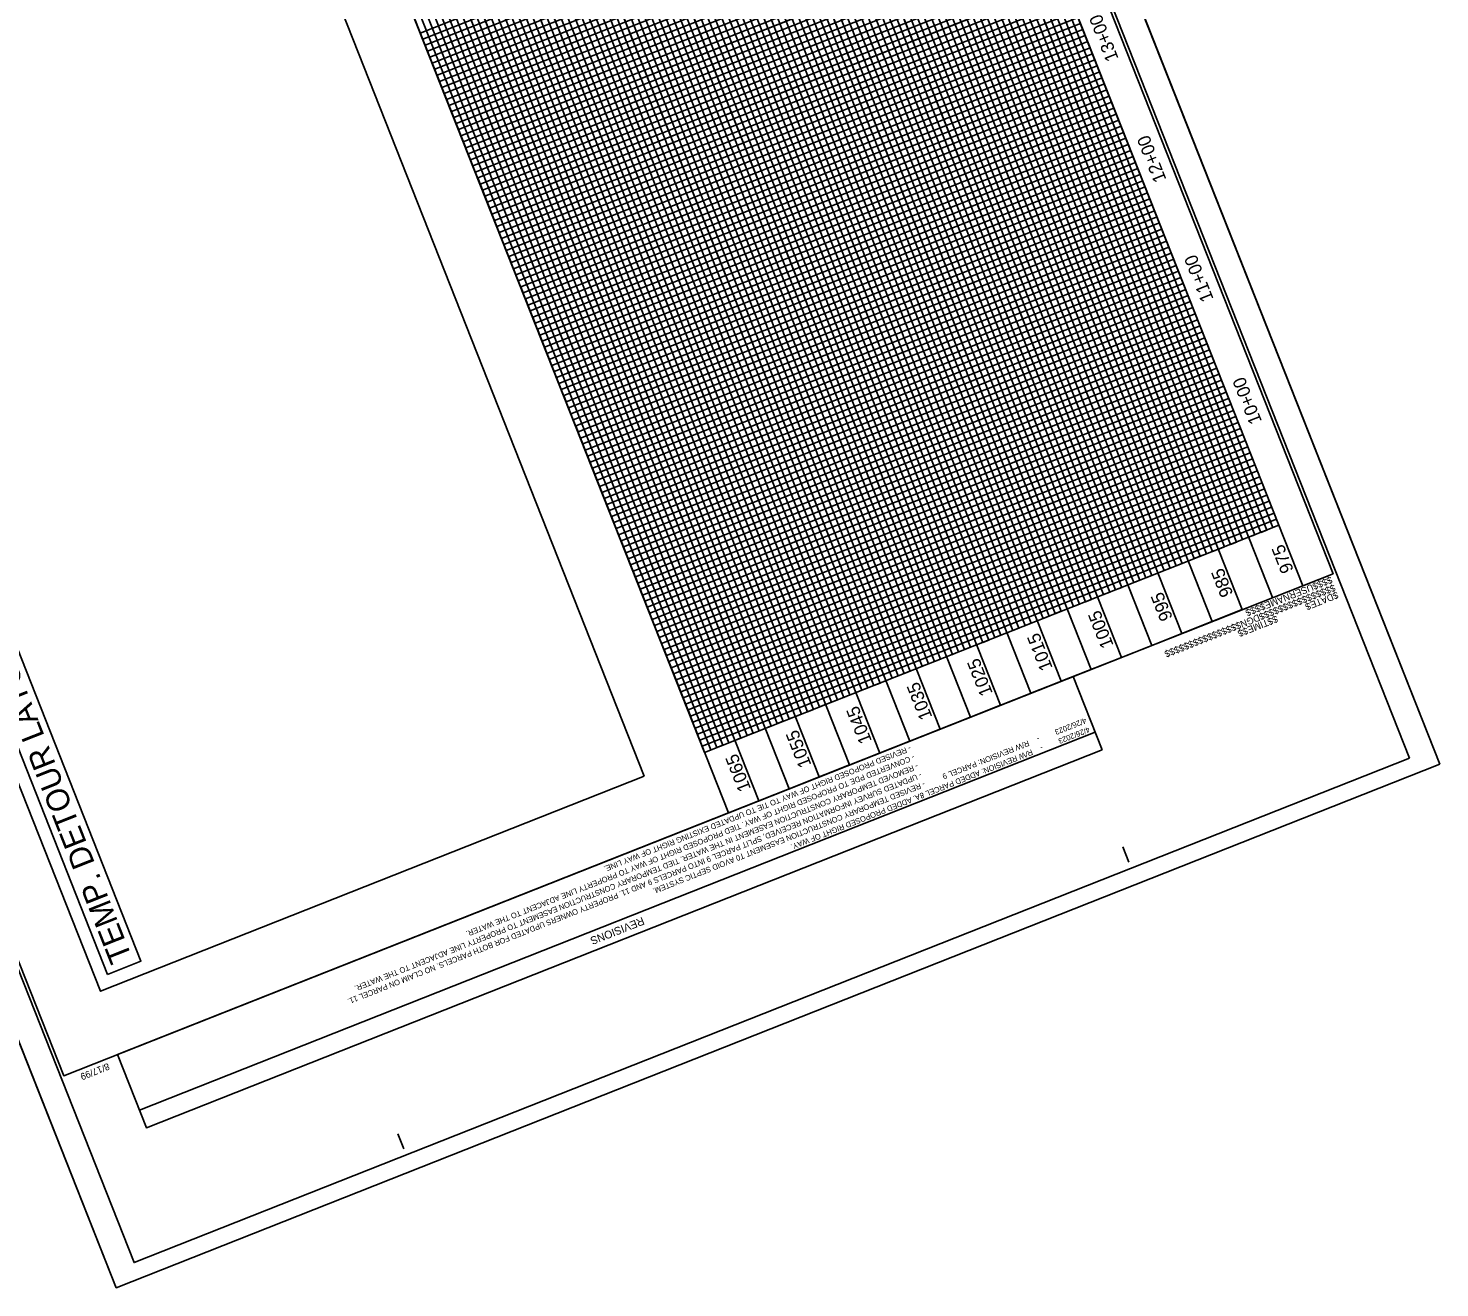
# Model space of a CAD drawing. Extents: x 1250120 to 1251758, y 748130 to 750098.
# Drawn here: x 1250672 to 1251758, y 748130 to 749099 of the extents above; entities that cross this region are included whole.
import ezdxf

# ---------------------------------------------------------------- set-up
doc = ezdxf.new("R2010")
doc.units = 0
for name, color, linetype in [('Exist Vertical Profile Horizontal Axis Label Major', 7, 'Continuous'), ('Exist Vertical Profile Vertical Axis Label', 7, 'Continuous'), ('Prop DSN Text', 7, 'Continuous'), ('Sheet Block Revision CELL', 7, 'Continuous'), ('Sheet Block System Information CELL', 7, 'Continuous'), ('Sheet Cutting Line CELL', 7, 'Continuous'), ('Sheet Detail CELL', 7, 'Continuous'), ('Sheet DOT Grid CELL', 7, 'Continuous'), ('Sheet Layout Plan Border', 7, 'Continuous'), ('Sheet Layout Profile Border Port 2', 7, 'Continuous'), ('Sheet Plan And Profile CELL', 7, 'Continuous'), ('Sheet Plot Border Inside CELL', 7, 'Continuous'), ('Sheet Plot Border Outside CELL', 7, 'Continuous'), ('Sheet Profile Grid Major CELL', 7, 'Continuous'), ('Sheet Profile Grid Middle CELL', 7, 'Continuous'), ('Sheet Profile Grid Minor CELL', 7, 'Continuous')]:
    doc.layers.add(name, color=color, linetype=linetype)

msp = doc.modelspace()

# ---------------------------------------------------------------- linework, layer by layer
at = {"layer": 'Sheet Block Revision CELL'}
msp.add_line((1251492.5, 748557.2), (1250757.2, 748266.4), dxfattribs=at)
msp.add_lwpolyline([(1251497.8, 748543.6), (1250762.6, 748252.9), (1250740.3, 748309.2), (1251475.6, 748599.9)], close=True, dxfattribs=at)
at = {"layer": 'Sheet Block System Information CELL'}
msp.add_line((1251675.5, 748679), (1251675.5, 748679), dxfattribs=at)
at = {"layer": 'Sheet Cutting Line CELL'}
for p, q in [((1251757.6, 748532.4), (1251138.6, 750098)), ((1250120.3, 749695.3), (1250739.4, 748129.8)), ((1250739.4, 748129.8), (1251757.6, 748532.4))]:
    msp.add_line(p, q, dxfattribs=at)
at = {"layer": 'Sheet Detail CELL'}
msp.add_lwpolyline([(1250732.8, 748370.8), (1250758.4, 748380.9), (1250644.4, 748669), (1250618.8, 748658.9)], close=True, dxfattribs=at)
at = {"layer": 'Sheet DOT Grid CELL'}
for p, q in [((1251629, 748660.6), (1251077.4, 750055.5)), ((1251582.5, 748642.2), (1251030.9, 750037.1)), ((1251536, 748623.8), (1250984.4, 750018.7)), ((1251489.5, 748605.4), (1250937.9, 750000.4)), ((1251443, 748587.1), (1250891.4, 749982)), ((1251396.5, 748568.7), (1250844.9, 749963.6)), ((1251350, 748550.3), (1250798.5, 749945.2)), ((1251303.5, 748531.9), (1250752, 749926.8)), ((1251257, 748513.5), (1250705.5, 749908.4)), ((1251210.5, 748495.1), (1250659, 749890)), ((1250989.9, 749053.1), (1251431.6, 749227.8)), ((1251008.3, 749006.6), (1251450, 749181.3)), ((1251026.7, 748960.1), (1251468.4, 749134.8)), ((1251045.1, 748913.6), (1251486.8, 749088.3)), ((1251063.4, 748867.1), (1251505.2, 749041.8)), ((1251081.8, 748820.6), (1251523.5, 748995.3)), ((1251100.2, 748774.1), (1251541.9, 748948.8)), ((1251118.6, 748727.6), (1251560.3, 748902.3)), ((1251137, 748681.1), (1251578.7, 748855.8)), ((1251155.4, 748634.6), (1251597.1, 748809.3)), ((1251173.8, 748588.1), (1251615.5, 748762.8)), ((1251192.1, 748541.6), (1251633.9, 748716.3))]:
    msp.add_line(p, q, dxfattribs=at)
at = {"layer": 'Sheet Layout Plan Border'}
msp.add_lwpolyline([(1251145.6, 748523.2), (1250727.2, 748357.8), (1250285.9, 749473.7), (1250436.1, 749533), (1250362.5, 749719.1), (1250630.8, 749825.2)], close=True, dxfattribs=at)
at = {"layer": 'Sheet Layout Profile Border Port 2'}
msp.add_lwpolyline([(1251192.1, 748541.6), (1250677.3, 749843.5), (1251119.1, 750018.2), (1251633.9, 748716.3)], close=True, dxfattribs=at)
at = {"layer": 'Sheet Plan And Profile CELL'}
for p, q in [((1251100.7, 750064.7), (1251652.2, 748669.8)), ((1251675.5, 748679), (1251675.5, 748679)), ((1251675.5, 748679), (1251675.5, 748679)), ((1251675.5, 748679), (1251675.5, 748679)), ((1251675.5, 748679), (1251675.5, 748679)), ((1251675.5, 748679), (1251675.5, 748679)), ((1251518.5, 748457.2), (1251513.9, 748468.9)), ((1250960.6, 748236.6), (1250956, 748248.2))]:
    msp.add_line(p, q, dxfattribs=at)
msp.add_lwpolyline([(1250147.5, 749687.8), (1250699.1, 748292.9), (1251675.5, 748679), (1251123.9, 750073.9)], close=True, dxfattribs=at)
at = {"layer": 'Sheet Plot Border Inside CELL'}
msp.add_lwpolyline([(1251734.3, 748537.2), (1251121.7, 750086.4), (1250140.6, 749698.5), (1250753.2, 748149.2)], close=True, dxfattribs=at)
at = {"layer": 'Sheet Plot Border Outside CELL'}
msp.add_lwpolyline([(1251757.6, 748532.4), (1251138.6, 750098), (1250120.3, 749695.3), (1250739.4, 748129.8)], close=True, dxfattribs=at)
at = {"layer": 'Sheet Profile Grid Major CELL'}
for points in [[(1251077.4, 750055.5), (1251629, 748660.6)], [(1250984.4, 750018.7), (1251536, 748623.8), (1251582.5, 748642.2), (1251030.9, 750037.1)], [(1250891.4, 749982), (1251443, 748587.1), (1251489.5, 748605.4), (1250937.9, 750000.4)], [(1250798.5, 749945.2), (1251350, 748550.3), (1251396.5, 748568.7), (1250844.9, 749963.6)], [(1250705.5, 749908.4), (1251257, 748513.5), (1251303.5, 748531.9), (1250752, 749926.8)], [(1251210.5, 748495.1), (1250659, 749890)], [(1251450, 749181.3), (1251008.3, 749006.6), (1250989.9, 749053.1), (1251431.6, 749227.8)], [(1251486.8, 749088.3), (1251045.1, 748913.6), (1251026.7, 748960.1), (1251468.4, 749134.8)], [(1251523.5, 748995.3), (1251081.8, 748820.6), (1251063.4, 748867.1), (1251505.2, 749041.8)], [(1251560.3, 748902.3), (1251118.6, 748727.6), (1251100.2, 748774.1), (1251541.9, 748948.8)], [(1251597.1, 748809.3), (1251155.4, 748634.6), (1251137, 748681.1), (1251578.7, 748855.8)], [(1251633.9, 748716.3), (1251192.1, 748541.6), (1251173.8, 748588.1), (1251615.5, 748762.8)], [(1251210.5, 748495.1), (1251652.2, 748669.8)]]:
    msp.add_lwpolyline(points, dxfattribs=at)
at = {"layer": 'Sheet Profile Grid Middle CELL'}
for p, q in [((1251605.7, 748651.4), (1251054.2, 750046.3)), ((1251007.7, 750027.9), (1251559.2, 748633)), ((1251512.8, 748614.6), (1250961.2, 750009.6)), ((1250914.7, 749991.2), (1251466.3, 748596.3)), ((1251419.8, 748577.9), (1250868.2, 749972.8)), ((1250821.7, 749954.4), (1251373.3, 748559.5)), ((1251326.8, 748541.1), (1250775.2, 749936)), ((1250728.7, 749917.6), (1251280.3, 748522.7)), ((1251233.8, 748504.3), (1250682.2, 749899.2)), ((1251559.2, 748633), (1251605.7, 748651.4)), ((1251466.3, 748596.3), (1251512.8, 748614.6)), ((1251373.3, 748559.5), (1251419.8, 748577.9)), ((1251280.3, 748522.7), (1251326.8, 748541.1))]:
    msp.add_line(p, q, dxfattribs=at)
for points in [[(1251440.8, 749204.5), (1250999.1, 749029.9), (1250980.7, 749076.3), (1251422.4, 749251)], [(1251477.6, 749111.5), (1251035.9, 748936.9), (1251017.5, 748983.4), (1251459.2, 749158)], [(1251514.4, 749018.5), (1251072.6, 748843.9), (1251054.2, 748890.4), (1251496, 749065)], [(1251551.1, 748925.5), (1251109.4, 748750.9), (1251091, 748797.4), (1251532.7, 748972)], [(1251587.9, 748832.5), (1251146.2, 748657.9), (1251127.8, 748704.4), (1251569.5, 748879)], [(1251624.7, 748739.5), (1251182.9, 748564.9), (1251164.6, 748611.4), (1251606.3, 748786)]]:
    msp.add_lwpolyline(points, dxfattribs=at)
at = {"layer": 'Sheet Profile Grid Minor CELL'}
for points in [[(1251629.2, 748714.5), (1251114.4, 750016.4), (1251109.8, 750014.5), (1251624.6, 748712.6), (1251619.9, 748710.8), (1251105.1, 750012.7), (1251100.5, 750010.9), (1251615.3, 748708.9), (1251610.6, 748707.1), (1251606, 748705.3), (1251091.2, 750007.2), (1251086.5, 750005.3), (1251601.3, 748703.4), (1251596.7, 748701.6), (1251081.9, 750003.5), (1251077.2, 750001.7), (1251592, 748699.7), (1251587.4, 748697.9), (1251582.7, 748696.1), (1251067.9, 749998), (1251063.3, 749996.1), (1251578.1, 748694.2), (1251573.4, 748692.4), (1251058.6, 749994.3)], [(1251573.4, 748692.4), (1251568.8, 748690.6), (1251054, 749992.5)], [(1251035.4, 749985.1), (1251550.2, 748683.2), (1251545.5, 748681.4), (1251030.7, 749983.3)], [(1251044.7, 749988.8), (1251559.5, 748686.9), (1251554.8, 748685), (1251040, 749987)], [(1250998.2, 749970.4), (1251513, 748668.5), (1251508.3, 748666.7), (1250993.5, 749968.6)], [(1251012.1, 749975.9), (1251526.9, 748674), (1251522.3, 748672.2), (1251007.5, 749974.1)], [(1251021.4, 749979.6), (1251536.2, 748677.7), (1251531.6, 748675.8), (1251016.8, 749977.8)], [(1250974.9, 749961.2), (1251489.7, 748659.3), (1251485.1, 748657.5), (1250970.3, 749959.4)], [(1250988.9, 749966.7), (1251503.7, 748664.8), (1251499, 748663), (1250984.2, 749964.9)], [(1250942.4, 749948.3), (1251457.2, 748646.4), (1251452.5, 748644.6), (1250937.7, 749946.5)], [(1250951.7, 749952), (1251466.5, 748650.1), (1251461.8, 748648.3), (1250947, 749950.2)], [(1250965.6, 749957.5), (1251480.4, 748655.6), (1251475.8, 748653.8), (1250961, 749955.7)], [(1250919.1, 749939.2), (1251433.9, 748637.2), (1251429.3, 748635.4), (1250914.5, 749937.3)], [(1250928.4, 749942.8), (1251443.2, 748640.9), (1251438.6, 748639.1), (1250923.8, 749941)], [(1250895.9, 749930), (1251410.7, 748628), (1251406, 748626.2), (1250891.2, 749928.1)], [(1250905.2, 749933.6), (1251420, 748631.7), (1251415.3, 748629.9), (1250900.5, 749931.8)], [(1250872.6, 749920.8), (1251387.4, 748618.9), (1251382.8, 748617), (1250868, 749918.9)], [(1250881.9, 749924.4), (1251396.7, 748622.5), (1251392.1, 748620.7), (1250877.3, 749922.6)], [(1250835.4, 749906.1), (1251350.2, 748604.1), (1251345.6, 748602.3), (1250830.8, 749904.2)], [(1250849.4, 749911.6), (1251364.2, 748609.7), (1251359.5, 748607.8), (1250844.7, 749909.7)], [(1250858.7, 749915.3), (1251373.5, 748613.3), (1251368.8, 748611.5), (1250854, 749913.4)], [(1250812.2, 749896.9), (1251327, 748594.9), (1251322.3, 748593.1), (1250807.5, 749895)], [(1250826.1, 749902.4), (1251340.9, 748600.5), (1251336.3, 748598.6), (1250821.5, 749900.5)], [(1250779.6, 749884), (1251294.4, 748582.1), (1251289.8, 748580.2), (1250775, 749882.2)], [(1250788.9, 749887.7), (1251303.7, 748585.8), (1251299.1, 748583.9), (1250784.3, 749885.8)], [(1250802.9, 749893.2), (1251317.7, 748591.3), (1251313, 748589.4), (1250798.2, 749891.4)], [(1250751.7, 749873), (1251266.5, 748571), (1251261.9, 748569.2), (1251257.2, 748567.4), (1250742.4, 749869.3)], [(1250761, 749876.6), (1251275.8, 748574.7), (1251271.2, 748572.9), (1250756.4, 749874.8)], [(1251289.8, 748580.2), (1251285.1, 748578.4), (1251280.5, 748576.6), (1250765.7, 749878.5)], [(1250728.5, 749863.8), (1251243.3, 748561.9), (1251238.6, 748560), (1251234, 748558.2), (1250719.2, 749860.1)], [(1250737.8, 749867.5), (1251252.6, 748565.5), (1251247.9, 748563.7), (1250733.1, 749865.6)], [(1250705.2, 749854.6), (1251220, 748552.7), (1251215.4, 748550.8), (1251210.7, 748549), (1250695.9, 749850.9)], [(1250714.5, 749858.3), (1251229.3, 748556.3), (1251224.7, 748554.5), (1250709.9, 749856.4)], [(1250682, 749845.4), (1251196.8, 748543.5)], [(1250691.3, 749849.1), (1251206.1, 748547.1), (1251201.4, 748545.3), (1250686.6, 749847.2)], [(1251416.9, 749265), (1250975.2, 749090.3), (1250973.3, 749094.9), (1251415.1, 749269.6)], [(1251420.6, 749255.7), (1250978.9, 749081), (1250977, 749085.6), (1251418.7, 749260.3)], [(1251426.1, 749241.7), (1250984.4, 749067), (1250982.5, 749071.7), (1251424.3, 749246.4)], [(1251429.8, 749232.4), (1250988.1, 749057.7), (1250986.2, 749062.4), (1251427.9, 749237.1)], [(1251435.3, 749218.5), (1250993.6, 749043.8), (1250991.7, 749048.4), (1251433.5, 749223.1)], [(1251439, 749209.2), (1250997.3, 749034.5), (1250995.4, 749039.2), (1251437.1, 749213.8)], [(1251444.5, 749195.2), (1251002.8, 749020.6), (1251000.9, 749025.2), (1251442.6, 749199.9)], [(1251448.2, 749185.9), (1251006.4, 749011.3), (1251004.6, 749015.9), (1251446.3, 749190.6)], [(1251453.7, 749172), (1251012, 748997.3), (1251010.1, 749002), (1251451.8, 749176.6)], [(1251457.4, 749162.7), (1251015.6, 748988), (1251013.8, 748992.7), (1251455.5, 749167.3)], [(1251462.9, 749148.7), (1251021.2, 748974.1), (1251019.3, 748978.7), (1251461, 749153.4)], [(1251466.6, 749139.4), (1251024.8, 748964.8), (1251023, 748969.4), (1251464.7, 749144.1)], [(1251472.1, 749125.5), (1251030.3, 748950.8), (1251028.5, 748955.5), (1251470.2, 749130.1)], [(1251475.7, 749116.2), (1251034, 748941.5), (1251032.2, 748946.2), (1251473.9, 749120.8)], [(1251481.3, 749102.2), (1251039.5, 748927.6), (1251037.7, 748932.2), (1251479.4, 749106.9)], [(1251484.9, 749092.9), (1251043.2, 748918.3), (1251041.4, 748922.9), (1251483.1, 749097.6)], [(1251490.5, 749079), (1251048.7, 748904.3), (1251046.9, 748909), (1251488.6, 749083.6)], [(1251494.1, 749069.7), (1251052.4, 748895), (1251050.6, 748899.7), (1251492.3, 749074.3)], [(1251499.6, 749055.7), (1251057.9, 748881.1), (1251056.1, 748885.7), (1251497.8, 749060.4)], [(1251503.3, 749046.4), (1251061.6, 748871.8), (1251059.8, 748876.4), (1251501.5, 749051.1)], [(1251508.8, 749032.5), (1251067.1, 748857.8), (1251065.3, 748862.5), (1251507, 749037.1)], [(1251512.5, 749023.2), (1251070.8, 748848.5), (1251069, 748853.2), (1251510.7, 749027.8)], [(1251518, 749009.2), (1251076.3, 748834.6), (1251074.5, 748839.2), (1251516.2, 749013.9)], [(1251521.7, 748999.9), (1251080, 748825.3), (1251078.1, 748829.9), (1251519.9, 749004.6)], [(1251527.2, 748986), (1251085.5, 748811.3), (1251083.7, 748816), (1251525.4, 748990.6)], [(1251530.9, 748976.7), (1251089.2, 748802), (1251087.3, 748806.7), (1251529.1, 748981.3)], [(1251536.4, 748962.7), (1251094.7, 748788.1), (1251092.9, 748792.7), (1251534.6, 748967.4)], [(1251540.1, 748953.4), (1251098.4, 748778.8), (1251096.5, 748783.4), (1251538.3, 748958.1)], [(1251545.6, 748939.5), (1251103.9, 748764.8), (1251102, 748769.5), (1251543.8, 748944.1)], [(1251549.3, 748930.2), (1251107.6, 748755.5), (1251105.7, 748760.2), (1251547.4, 748934.8)], [(1251554.8, 748916.2), (1251113.1, 748741.6), (1251111.2, 748746.2), (1251553, 748920.9)], [(1251558.5, 748906.9), (1251116.8, 748732.3), (1251114.9, 748736.9), (1251556.6, 748911.6)], [(1251564, 748893), (1251122.3, 748718.3), (1251120.4, 748723), (1251562.2, 748897.6)], [(1251567.7, 748883.7), (1251125.9, 748709), (1251124.1, 748713.7), (1251565.8, 748888.3)], [(1251573.2, 748869.7), (1251131.5, 748695.1), (1251129.6, 748699.7), (1251571.3, 748874.4)], [(1251576.9, 748860.4), (1251135.1, 748685.8), (1251133.3, 748690.4), (1251575, 748865.1)], [(1251582.4, 748846.5), (1251140.7, 748671.8), (1251138.8, 748676.5), (1251580.5, 748851.1)], [(1251586.1, 748837.2), (1251144.3, 748662.5), (1251142.5, 748667.2), (1251584.2, 748841.8)], [(1251591.6, 748823.2), (1251149.8, 748648.6), (1251148, 748653.2), (1251589.7, 748827.9)], [(1251595.2, 748813.9), (1251153.5, 748639.3), (1251151.7, 748643.9), (1251593.4, 748818.6)], [(1251600.8, 748800), (1251159, 748625.3), (1251157.2, 748630), (1251598.9, 748804.6)], [(1251604.4, 748790.7), (1251162.7, 748616), (1251160.9, 748620.7), (1251602.6, 748795.3)], [(1251610, 748776.7), (1251168.2, 748602.1), (1251166.4, 748606.7), (1251608.1, 748781.4)], [(1251613.6, 748767.4), (1251171.9, 748592.8), (1251170.1, 748597.4), (1251611.8, 748772.1)], [(1251619.1, 748753.5), (1251177.4, 748578.8), (1251175.6, 748583.5), (1251617.3, 748758.1)], [(1251622.8, 748744.2), (1251181.1, 748569.5), (1251179.3, 748574.2), (1251621, 748748.8)], [(1251628.3, 748730.2), (1251186.6, 748555.6), (1251184.8, 748560.2), (1251626.5, 748734.9)], [(1251632, 748720.9), (1251190.3, 748546.3), (1251188.5, 748550.9), (1251630.2, 748725.6)]]:
    msp.add_lwpolyline(points, dxfattribs=at)

# ---------------------------------------------------------------- texts
at = {"layer": 'Exist Vertical Profile Horizontal Axis Label Major'}
for s, p in [('13+00', (1251510.7, 749075.3)), ('12+00', (1251547.5, 748982.3)), ('11+00', (1251583.8, 748890.4)), ('10+00', (1251621, 748796.3))]:
    msp.add_text(s, height=10, rotation=111.5743, dxfattribs=at).set_placement(p)
at = {"layer": 'Exist Vertical Profile Vertical Axis Label'}
for s, p in [('975', (1251645.4, 748681.7)), ('985', (1251598.9, 748663.4)), ('995', (1251552.4, 748645)), ('1005', (1251506.9, 748624)), ('1015', (1251460, 748606.7)), ('1025', (1251413.9, 748587.2)), ('1035', (1251367.4, 748568.9)), ('1045', (1251320.9, 748550.5)), ('1055', (1251274.4, 748532.1)), ('1065', (1251227.9, 748513.7))]:
    msp.add_text(s, height=10, rotation=111.5743, dxfattribs=at).set_placement(p)
at = {"layer": 'Prop DSN Text'}
msp.add_text('TEMP. DETOUR LAYOUT', height=17.5, rotation=111.5743, dxfattribs=at).set_placement((1250751.9, 748383.7))
at = {"layer": 'Sheet Block Revision CELL'}
for s, height, p in [('4/26/2023', 4.3, (1251484.8, 748568.3)), ('4/26/2023', 4.3, (1251487.5, 748561.4)), ('R/W REVISION: PARCEL 9', 4.3, (1251440.8, 748550.9)), ('-', 4.3, (1251448.8, 748554.1)), ('- CONVERTED PDE TO PROPOSED RIGHT OF WAY. TIED PROPOSED RIGHT OF WAY TO PROPERTY LINE ADJACENT TO THE WATER.', 4.3, (1251352.6, 748540)), ('- REVISED PROPOSED RIGHT OF WAY TO TIE TO UPDATED EXISTING RIGHT OF WAY LINE.', 4.3, (1251349.9, 748546.9)), ('R/W REVISION: ADDED PARCEL 8A. ADDED PROPOSED RIGHT OF WAY.', 4.3, (1251443.5, 748544)), ('-', 4.3, (1251451.5, 748547.2)), ('- REMOVED TEMPORARY CONSTRUCTION EASEMENT IN THE WATER. TIED TEMPORARY CONSTRUCTION EASEMENT TO PROPERTY LINE ADJACENT TO THE WATER.', 4.3, (1251355.4, 748533.1)), ('- UPDATED SURVEY INFORMATION RECEIVED, SPLIT PARCEL 9 INTO PARCELS 9 AND 11. PROPERTY OWNERS UPDATED FOR BOTH PARCELS. NO CLAIM ON PARCEL 11.', 4.3, (1251358.1, 748526.2)), ('- REVISED TEMPORARY CONSTRUCTION EASEMENT T0 AVOID SEPTIC SYSTEM.', 4.3, (1251360.8, 748519.3)), ('REVISIONS', 6, (1251144.2, 748415.1))]:
    msp.add_text(s, height=height, rotation=201.5743, dxfattribs=at).set_placement(p)
at = {"layer": 'Sheet Block System Information CELL'}
for s, p in [('$$$$$$$$$$$$$$$$DGN$$$$$$$$$$$$$$$$', (1251676.1, 748671)), ('$$$$USERNAME$$$$', (1251673.7, 748677.1)), ('$DATE$', (1251678.3, 748665.4)), ('$$TIME$$', (1251631.8, 748647))]:
    msp.add_text(s, height=5.25, rotation=201.5743, dxfattribs=at).set_placement(p)
at = {"layer": 'Sheet Plan And Profile CELL'}
msp.add_text('8/17/99', height=5.25, rotation=201.5743, dxfattribs=at).set_placement((1250733, 748302.8))

doc.saveas('drawing.dxf')
